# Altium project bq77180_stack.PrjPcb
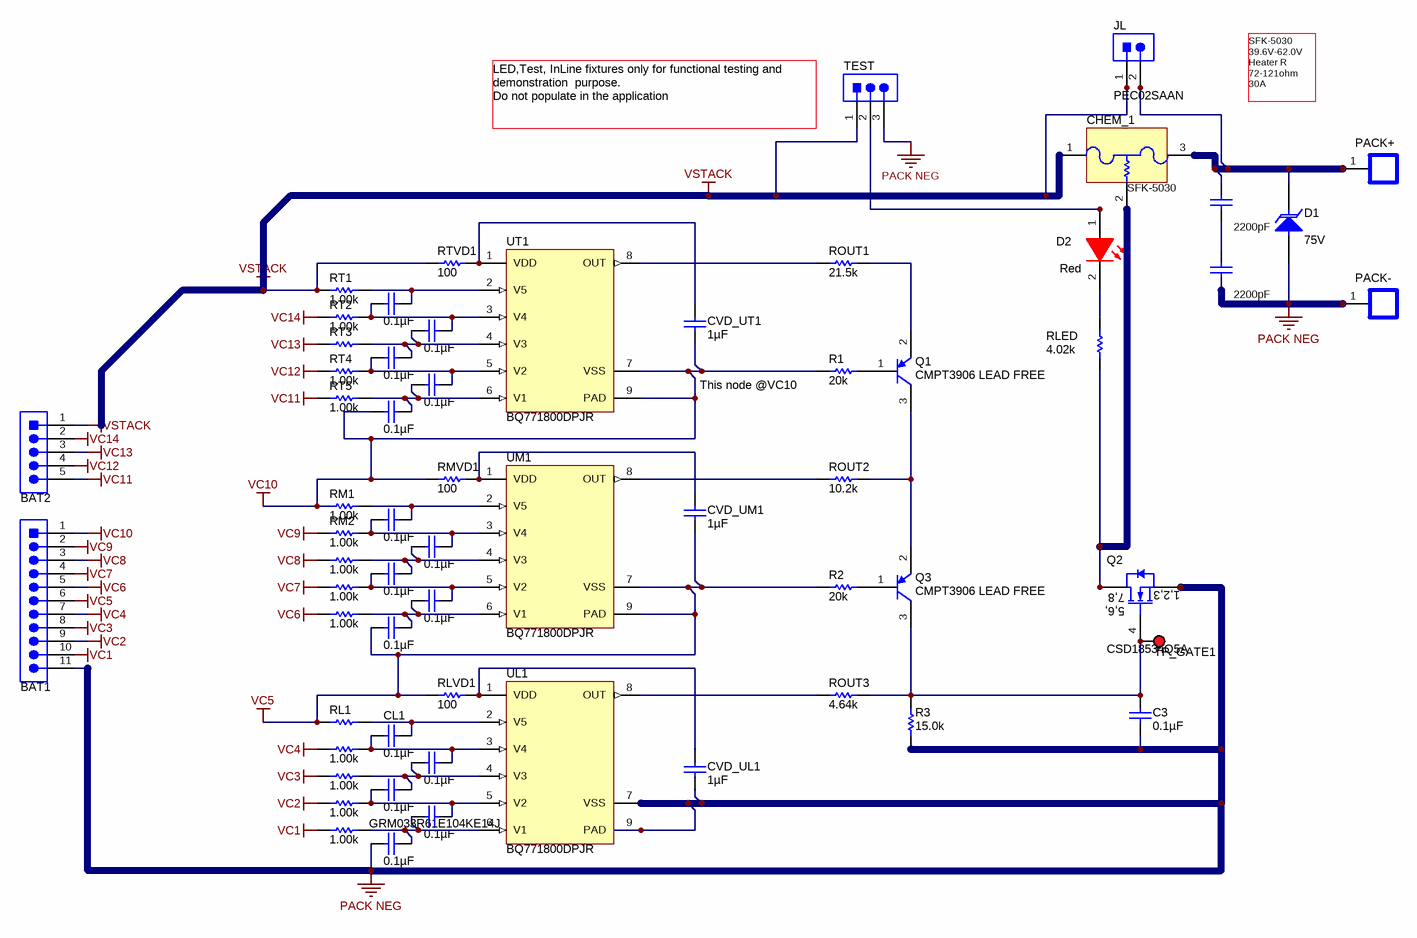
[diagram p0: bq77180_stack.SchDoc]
TID: TIDA00108; TechSupport: VISH NADARAJAH; SCH_Rev: 1.0; PRJ_Title: bq77180-STACK PROTECTOR 75v; PRJ_Number: bq77180; PRJ_Engineer: Vish Nadarajah; PRJ_Customer: TIDA-00108; PCB_Rev: 1.0; PCB_Layout: Vish Nadarajah; EVM_orderable: N/A; CopyrightYear: 2016
1 sheet, 62 parts. Net scope: global (net labels, ports and power ports of the same name join across sheets).
Board file: bq77180_stack.PcbDoc

## Sheet bq77180_stack.SchDoc
size 431 x 279 mm; VersionControl_RevNumber: 1.0; Date: Not shown in title block; ApprovedBy: Not shown in title block; CheckedBy: Willy Massoth; Author: Vish Nadarajah; CompanyName: TI-BMS-M&P; DrawnBy: Vish Nadarajah; Engineer: Vish Nadarajah; Organization: TI BMS,M&P; Address1: 12500 TI BLVD; Address2: DALLAS, TX 75243; Address3: Not shown in title block; Address4: Not shown in title block; DocumentNumber: 1; Revision: Use project parameter SCH_Rev; SheetNumber: 2; SheetTotal: 3; PageSetup: Record=PageOptions¦CenterHorizontal=True¦CenterVertical=True¦PrintScale=0.62¦XCorrection=1.00¦YCorrection=1.00¦PrintKind=0¦BorderSize=5000000¦LeftOffset=0¦BottomOffset=0¦Orientation=2¦PaperLength=1000¦PaperWidth=1000¦Scale=100¦PaperSource=15¦PrintQuality=600¦MediaType=1¦DitherType=10¦PrintScaleMode=1¦PaperKind=Letter

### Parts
BAT1  395021011  [HEADER_395021011]  (value not drawn)
BAT2  395021005  [HEADER_395021005]  (value not drawn)
C1  ValueDisplayed: 2200pF  [1206]  (hidden comment: 12061A222JAT2A)
C2  ValueDisplayed: 2200pF  [1206]  (hidden comment: 12061A222JAT2A)
C3  ValueDisplayed: 0.1µF  [0201_033]  (hidden comment: GRM033R61E104KE14J)
CHEM_1  SFK-5030  [FUSE_SFK-xx30x]
CL1  ValueDisplayed: 0.1µF  [0201_033]  (hidden comment: GRM033R61E104KE14J)
CL2  ValueDisplayed: 0.1µF  [0201_033]  (hidden comment: GRM033R61E104KE14J)
CL3  ValueDisplayed: 0.1µF  [0201_033]  (hidden comment: GRM033R61E104KE14J)
CL4  ValueDisplayed: 0.1µF  [0201_033]  (hidden comment: GRM033R61E104KE14J)
CL5  GRM033R61E104KE14J  ValueDisplayed: 0.1µF  [0201_033]
CM1  ValueDisplayed: 0.1µF  [0201_033]  (hidden comment: GRM033R61E104KE14J)
CM2  ValueDisplayed: 0.1µF  [0201_033]  (hidden comment: GRM033R61E104KE14J)
CM3  ValueDisplayed: 0.1µF  [0201_033]  (hidden comment: GRM033R61E104KE14J)
CM4  ValueDisplayed: 0.1µF  [0201_033]  (hidden comment: GRM033R61E104KE14J)
CM5  ValueDisplayed: 0.1µF  [0201_033]  (hidden comment: GRM033R61E104KE14J)
CT1  ValueDisplayed: 0.1µF  [0201_033]  (hidden comment: GRM033R61E104KE14J)
CT2  ValueDisplayed: 0.1µF  [0201_033]  (hidden comment: GRM033R61E104KE14J)
CT3  ValueDisplayed: 0.1µF  [0201_033]  (hidden comment: GRM033R61E104KE14J)
CT4  ValueDisplayed: 0.1µF  [0201_033]  (hidden comment: GRM033R61E104KE14J)
CT5  ValueDisplayed: 0.1µF  [0201_033]  (hidden comment: GRM033R61E104KE14J)
CVD_UL1  ValueDisplayed: 1µF  [0402]  (hidden comment: C1005X5R1E105K050BC)
CVD_UM1  ValueDisplayed: 1µF  [0402]  (hidden comment: C1005X5R1E105K050BC)
CVD_UT1  ValueDisplayed: 1µF  [0402]  (hidden comment: C1005X5R1E105K050BC)
D1  value 75V  [SMC]  (hidden comment: 5.0SMDJ75A)
D2  value Red  [1111C_Red]  (hidden comment: BR1111C-TR)
JL  PEC02SAAN  [CONN_PEC02SAAN]
PACK+  8199  [SCREW_TERMINAL_8199]  (value not drawn)
PACK-  8199  [SCREW_TERMINAL_8199]  (value not drawn)
Q1  CMPT3906 LEAD FREE  [SOT-23]
Q2  CSD18534Q5A  [TRANS_NexFET_Q5A]
Q3  CMPT3906 LEAD FREE  [SOT-23]
R1  ValueDisplayed: 20k  [0402]  (hidden comment: CRCW040220K0JNED)
R2  ValueDisplayed: 20k  [0402]  (hidden comment: CRCW040220K0JNED)
R3  ValueDisplayed: 15.0k  [0402]  (hidden comment: CRCW040215K0FKED)
RL1  RC0603FR-071KL  [0603]  (value not drawn)
RL2  ValueDisplayed: 1.00k  [0603]  (hidden comment: RC0603FR-071KL)
RL3  ValueDisplayed: 1.00k  [0603]  (hidden comment: RC0603FR-071KL)
RL4  ValueDisplayed: 1.00k  [0603]  (hidden comment: RC0603FR-071KL)
RL5  ValueDisplayed: 1.00k  [0603]  (hidden comment: RC0603FR-071KL)
RLED  ValueDisplayed: 4.02k  [1206]  (hidden comment: CRCW12064K02FKEA)
RLVD1  ValueDisplayed: 100  [0402]  (hidden comment: CRCW0402100RFKED)
RM1  ValueDisplayed: 1.00k  [0603]  (hidden comment: RC0603FR-071KL)
RM2  ValueDisplayed: 1.00k  [0603]  (hidden comment: RC0603FR-071KL)
RM3  ValueDisplayed: 1.00k  [0603]  (hidden comment: RC0603FR-071KL)
RM4  ValueDisplayed: 1.00k  [0603]  (hidden comment: RC0603FR-071KL)
RM5  ValueDisplayed: 1.00k  [0603]  (hidden comment: RC0603FR-071KL)
RMVD1  ValueDisplayed: 100  [0402]  (hidden comment: CRCW0402100RFKED)
ROUT1  ValueDisplayed: 21.5k  [0603]  (hidden comment: RC0603FR-0721K5L)
ROUT2  ValueDisplayed: 10.2k  [0603]  (hidden comment: RC0603FR-0710K2L)
ROUT3  ValueDisplayed: 4.64k  [0603]  (hidden comment: RC0603FR-074K64L)
RT1  ValueDisplayed: 1.00k  [0603]  (hidden comment: RC0603FR-071KL)
RT2  ValueDisplayed: 1.00k  [0603]  (hidden comment: RC0603FR-071KL)
RT3  RC0603FR-071KL  [0603]  (value not drawn)
RT4  ValueDisplayed: 1.00k  [0603]  (hidden comment: RC0603FR-071KL)
RT5  ValueDisplayed: 1.00k  [0603]  (hidden comment: RC0603FR-071KL)
RTVD1  ValueDisplayed: 100  [0402]  (hidden comment: CRCW0402100RFKED)
TEST  PBC03SGBN  [Sullins_xxC03SGBN]  (value not drawn)
TP_GATE1  5005  [Keystone5005]  (value not drawn)
UL1  BQ771800DPJR  [DPJ0008A]
UM1  BQ771800DPJR  [DPJ0008A]
UT1  BQ771800DPJR  [DPJ0008A]

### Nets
PACK NEG: BAT1.11 C2.2 C3.2 CL5.1 CVD_UL1.2 D1.2(A) PACK-.1 PACK-.2 PACK-.3 PACK-.4 PACK-.5 PACK-.6 Q2.1(S) Q2.2(S) Q2.3(S) R3.1 TEST.3 UL1.7(VSS) UL1.9(PAD)
VC1: BAT1.10 RL5.2
VC2: BAT1.9 RL4.2
VC3: BAT1.8 RL3.2
VC4: BAT1.7 RL2.2
VC5: BAT1.6 CM5.1 CVD_UM1.2 R2.2 RL1.2 RLVD1.2 UM1.7(VSS) UM1.9(PAD)
VC6: BAT1.5 RM5.2
VC7: BAT1.4 RM4.2
VC8: BAT1.3 RM3.2
VC9: BAT1.2 RM2.2
VC10: BAT1.1 CT5.1 CVD_UT1.2 R1.2 RM1.2 RMVD1.2 UT1.7(VSS) UT1.9(PAD)
VC11: BAT2.5 RT5.2
VC12: BAT2.4 RT4.2
VC13: BAT2.3 RT3.2
VC14: BAT2.2 RT2.2
VSTACK: BAT2.1 CHEM_1.1(Fuse) JL.1 RT1.2 RTVD1.2 TEST.1
NetC1_1: C1.1 CHEM_1.3(Fuse) D1.1(K) JL.2 PACK+.1 PACK+.2 PACK+.3 PACK+.4 PACK+.5 PACK+.6
NetC1_2: C1.2 C2.1
NetC3_1: C3.1 Q2.4(G) Q3.3(C) R3.2 ROUT3.1 TP_GATE1.1
NetCHEM_1_2: CHEM_1.2(Heater) Q2.5(D) Q2.6(D) Q2.7(D) Q2.8(D) Q2.9(D) RLED.1
NetCL1_1: CL1.1 CL2.2 RL2.1 UL1.3(V4)
NetCL1_2: CL1.2 RL1.1 UL1.2(V5)
NetCL2_1: CL2.1 CL3.2 RL3.1 UL1.4(V3)
NetCL3_1: CL3.1 CL4.1 RL4.1 UL1.5(V2)
NetCL4_2: CL4.2 CL5.2 RL5.1 UL1.6(V1)
NetCM1_1: CM1.1 CM2.2 RM2.1 UM1.3(V4)
NetCM1_2: CM1.2 RM1.1 UM1.2(V5)
NetCM2_1: CM2.1 CM3.2 RM3.1 UM1.4(V3)
NetCM3_1: CM3.1 CM4.1 RM4.1 UM1.5(V2)
NetCM4_2: CM4.2 CM5.2 RM5.1 UM1.6(V1)
NetCT1_1: CT1.1 CT2.2 RT2.1 UT1.3(V4)
NetCT1_2: CT1.2 RT1.1 UT1.2(V5)
NetCT2_1: CT2.1 CT3.2 RT3.1 UT1.4(V3)
NetCT3_1: CT3.1 CT4.1 RT4.1 UT1.5(V2)
NetCT4_2: CT4.2 CT5.2 RT5.1 UT1.6(V1)
NetCVD_UL1_1: CVD_UL1.1 RLVD1.1 UL1.1(VDD)
NetCVD_UM1_1: CVD_UM1.1 RMVD1.1 UM1.1(VDD)
NetCVD_UT1_1: CVD_UT1.1 RTVD1.1 UT1.1(VDD)
NetD2_1: D2.1(A) TEST.2
NetD2_2: D2.2(K) RLED.2
NetQ1_1: Q1.1(B) R1.1
NetQ1_2: Q1.2(E) ROUT1.1
NetQ1_3: Q1.3(C) Q3.2(E) ROUT2.1
NetQ3_1: Q3.1(B) R2.1
NetROUT1_2: ROUT1.2 UT1.8(OUT)
NetROUT2_2: ROUT2.2 UM1.8(OUT)
NetROUT3_2: ROUT3.2 UL1.8(OUT)

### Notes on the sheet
- (near TEST) LED,Test, InLine fixtures only for functional testing and demonstration  purpose.
  Do not populate in the application
- SFK-5030
  39.6V-62.0V
  Heater R 72-121ohm
  30A
- This node @VC10

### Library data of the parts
BAT1 = 395021011: Terminal block, 3.5mm, 11x1, R/A, TH; Manufacturer: Molex; SymbolCreator: a0799628
BAT2 = 395021005: Header (shrouded), 3.5mm, 5x1, R/A, TH; Manufacturer: Molex; SymbolCreator: a0412235
C1 C2 = 12061A222JAT2A: CAP, CERM, 2200 pF, 100 V, +/- 5%, C0G/NP0, 1206; Manufacturer: AVX; Polarized: N; CompType: Capacitor; Value: 2200pF; U/M: EA; Cap_F: 0.0000000022; Tolerance_%: 5; ESR_ohm: 0.173; Value1: 0.173 ohm; VDC_V: 100; Value2: 100V; TaMin_C: -55; TaMax_C: 125; SizeArea_mm2: 5.12; SizeAreaWB_mm2: 10.92; SizeX_mm: 3.2; SizeY_mm: 1.6; SizeZ_mm: 1.35; AEC Category: Q200
C3 CL1-CL5 CM1-CM5 CT1-CT5 = GRM033R61E104KE14J: CAP, CERM, 0.1 µF, 25 V, +/- 10%, X5R, 0201; Manufacturer: MuRata; Polarized: N; CompType: Capacitor; Value: 0.1uF; U/M: EA; Cap_F: 0.0000001; Tolerance_%: 10; Value1: Unknown; VDC_V: 25; Value2: 25V; TaMin_C: -55; TaMax_C: 85; Cap_Case: 0201; AEC Category: Q200
CHEM_1 = SFK-5030: Fuse, 30 A, 62 VDC, SMD; Manufacturer: Dexerials Corporation; SymbolCreator: x0208325; VDC_V: 62; Irating_A: 30; Rtyp_Ohm: 0.0015
CVD_UL1 CVD_UM1 CVD_UT1 = C1005X5R1E105K050BC: CAP, CERM, 1 µF, 25 V, +/- 10%, X5R, 0402; Manufacturer: TDK; Polarized: N; CompType: Capacitor; Value: 1uF; U/M: EA; Cap_F: 0.000001; Tolerance_%: 10; Value1: Unknown; VDC_V: 25; Value2: 25V; TaMin_C: -55; TaMax_C: 80; AEC Category: Q200
D1 = 5.0SMDJ75A: Diode, TVS, Uni, 75 V, 5000 W, SMC; Manufacturer: Littelfuse; U/M: EA; Power_W: 6.5; Vr_V: 75; Value1: 6.5W; SizeAreaWB_mm2: 83.2686; SizeArea_mm2: 50.5686; SizeX_mm: 8.13; SizeY_mm: 6.22; SizeZ_mm: 2.6; AEC Category: Q101
D2 = BR1111C-TR: LED, Red, SMD; Manufacturer: Stanley Electric Co., LTD; SymbolCreator: Altium; Vf_V: 1.7; Value2: 1.7V; Io_A: 0.02; Vr_V: 4; Ir_A: 0.0001; Tjmax_C: 85; Power_TotalModule: 0.0575; Value1: 0.0575W; U/M: EA
JL = PEC02SAAN: Header, 100mil, 2x1, Tin, TH; Manufacturer: Sullins Connector Solutions; SymbolCreator: a0412235; Pitch_mm: 2.54; Gender: Male; Shrouded: N; Row_Count: 1; Current_A: 3; Voltage_V: 1800; Cert_UL: Y
PACK+ PACK- = 8199: TERMINAL SCREW PC 30AMP, TH; Manufacturer: Keystone; SymbolCreator: a0799628; CompType: Screw Connector
Q1 Q3 = CMPT3906 LEAD FREE, Central Semiconductor: Transistor, PNP, 40 V, 0.2 A, SOT-23; CompType: BJT; PNP: 1; NPN: 0; Vceo_V: 40; Vcesat1_V: 0.25; Value: 40 V; IcRated_A: 0.2; Value1: 0.2 A; TaMin_C: -65; TaMax_C: 150; U/M: EA; AEC Category: Q101
Q2 = CSD18534Q5A: MOSFET, N-CH, 60 V, 50 A, SON 5x6mm; Manufacturer: Texas Instruments; Alternate Manufacturer: None; U/M: EA; ChType: N; Value: 60V; VdsMax_V: 60; Value1: 0.0098 ohm; Rdson45_ohm: 0.0098; Value2: 22 nC; QgTyp_nC: 22; Vgs_V: 2.3; IdsMax_A: 50; AEC Category: Q101; SizeAreaWB_mm2: 55.2; SizeArea_mm2: 29.4; SizeX_mm: 6; SizeY_mm: 4.9; SizeZ_mm: 1
R1 R2 = CRCW040220K0JNED: RES, 20 k, 5%, 0.063 W, 0402; Manufacturer: Vishay-Dale; CompType: Resistor; Value: 20k; Res_ohm: 20000; Value_Code: 20k0; Tolerance_%: 5; Power_W: 0.063; Value2: 0.063W; VDC_V: 50; TempCo: 200 ppm/C; EIA_Code: E24; U/M: EA; AEC Category: Q200; SizeArea_mm2: 0.5; SizeX_mm: 1; SizeZ_mm: 0.6
R3 = CRCW040215K0FKED: RES, 15.0 k, 1%, 0.063 W, 0402; Manufacturer: Vishay-Dale; CompType: Resistor; Value: 15.0k; Res_ohm: 15000; Value_Code: 15k0; Tolerance_%: 1; Power_W: 0.063; Value2: 0.063W; VDC_V: 50; TempCo: 100 ppm/C; EIA_Code: E96; U/M: EA; AEC Category: Q200; SizeArea_mm2: 0.5; SizeZ_mm: 0.6
RL1-RL5 RM1-RM5 RT1-RT5 = RC0603FR-071KL: RES, 1.00 k, 1%, 0.1 W, 0603; Manufacturer: Yageo America; CompType: Resistor; Value: 1.00k; Res_ohm: 1000; Value_Code: 1k00; Tolerance_%: 1; Power_W: 0.1; Value2: 0.1W; VDC_V: 150; TempCo: 200 ppm/C; EIA_Code: E96; U/M: EA; AEC Category: Q200
RLED = CRCW12064K02FKEA: RES, 4.02 k, 1%, 0.25 W, 1206; Manufacturer: Vishay-Dale; CompType: Resistor; Value: 4.02k; Res_ohm: 4020; Value_Code: 4k02; Tolerance_%: 1; Power_W: 0.25; Value2: 0.25W; VDC_V: 200; TempCo: 100 ppm/C; EIA_Code: E96; U/M: EA; AEC Category: Q200
RLVD1 RMVD1 RTVD1 = CRCW0402100RFKED: RES, 100, 1%, 0.063 W, 0402; Manufacturer: Vishay-Dale; CompType: Resistor; Value: 100; Value_Code: 100R; Tolerance_%: 1; Power_W: 0.063; Value2: 0.063W; VDC_V: 50; TempCo: 100 ppm/C; EIA_Code: E96; U/M: EA; AEC Category: Q200
ROUT1 = RC0603FR-0721K5L: RES, 21.5 k, 1%, 0.1 W, 0603; Manufacturer: Yageo America; CompType: Resistor; Value: 21.5k; Res_ohm: 21500; Value_Code: 21k5; Tolerance_%: 1; Power_W: 0.1; Value2: 0.1W; VDC_V: 150; TempCo: 200 ppm/C; EIA_Code: E96; U/M: EA; AEC Category: Q200; SizeArea_mm2: 1.28; SizeX_mm: 1.6; SizeY_mm: 0.8
ROUT2 = RC0603FR-0710K2L: RES, 10.2 k, 1%, 0.1 W, 0603; Manufacturer: Yageo America; CompType: Resistor; Value: 10.2k; Res_ohm: 10200; Value_Code: 10k2; Tolerance_%: 1; Power_W: 0.1; Value2: 0.1W; VDC_V: 150; TempCo: 200 ppm/C; EIA_Code: E96; U/M: EA; AEC Category: Q200; SizeArea_mm2: 1.28; SizeX_mm: 1.6; SizeY_mm: 0.8
ROUT3 = RC0603FR-074K64L: RES, 4.64 k, 1%, 0.1 W, 0603; Manufacturer: Yageo America; CompType: Resistor; Value: 4.64k; Res_ohm: 4640; Value_Code: 4k64; Tolerance_%: 1; Power_W: 0.1; Value2: 0.1W; VDC_V: 150; TempCo: 200 ppm/C; EIA_Code: E96; U/M: EA; AEC Category: Q200; SizeArea_mm2: 1.28; SizeX_mm: 1.6; SizeY_mm: 0.8
TEST = PBC03SGBN: Header, 2.54 mm, 3x1, Gold, R/A, TH; Manufacturer: Sullins Connector Solutions; SymbolCreator: a0799628; Pitch_mm: 2.54; Gender: Male; Shrouded: N; Row_Count: 1; Current_A: 3; Voltage_V: 1800; Cert_UL: Y
TP_GATE1 = 5005: Test Point, Compact, Red, TH; Manufacturer: Keystone; CompType: Test Point Loop; ContactFinish: Silver
UL1 UM1 UT1 = BQ771800DPJR: Overvoltage Protection for 2-Series to 5-Series Cell Li-Ion Batteries with Internal Delay Timer, DPJ0008A; Alternate PartNumber: BQ771800DPJT; Manufacturer: Texas Instruments; SymbolCreator: x0208325; CompType: IC; U/M: EA

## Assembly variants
001: not fitted FID1 FID2 FID3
